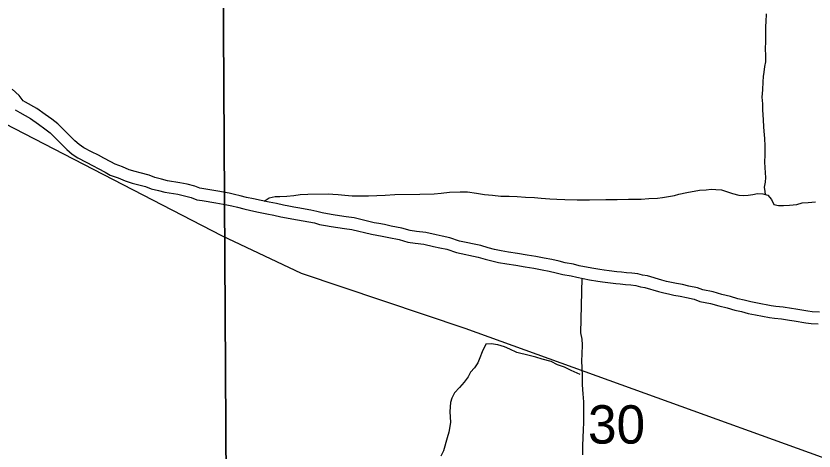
# Model space of a CAD drawing. Extents: x 0 to 34, y 0 to 22.
# Drawn here: x 3.385 to 4.256, y 19.88 to 20.355 of the extents above; entities that cross this region are included whole.
import ezdxf

# ---------------------------------------------------------------- set-up
doc = ezdxf.new("R2010")
doc.units = 0
for name, color, linetype in [('GM_X_Minor_River', 7, 'Continuous'), ('GM_X_Rail_Line', 7, 'Continuous'), ('GM_X_Section', 7, 'Continuous'), ('GM_X_Section_Text', 7, 'Continuous')]:
    doc.layers.add(name, color=color, linetype=linetype)

msp = doc.modelspace()

# ---------------------------------------------------------------- linework, layer by layer
at = {"layer": 'GM_X_Minor_River'}
for points in [[(4.20272, 20.16012), (4.2024, 20.16325), (4.20162, 20.16819), (4.20273, 20.17352), (4.20308, 20.17846), (4.20268, 20.18378), (4.20186, 20.19518), (4.20219, 20.20317), (4.20217, 20.20811), (4.20252, 20.21306), (4.2021, 20.22104), (4.2013, 20.22902), (4.20089, 20.23396), (4.20047, 20.24156), (4.20007, 20.24688), (4.19966, 20.25259), (4.19962, 20.25905), (4.19921, 20.26627), (4.19992, 20.27426), (4.20026, 20.28301), (4.20061, 20.28871), (4.20134, 20.29366), (4.20206, 20.29974), (4.20318, 20.30469), (4.20314, 20.31077), (4.20272, 20.31952), (4.20306, 20.32636), (4.203, 20.33853), (4.20297, 20.34347), (4.20333, 20.34842), (4.20366, 20.35716)], [(3.71354, 20.14163), (3.70699, 20.14283), (3.70091, 20.14395), (3.69477, 20.14507), (3.68838, 20.14617), (3.68275, 20.14727), (3.67698, 20.14833), (3.66946, 20.15017), (3.66161, 20.15171), (3.65265, 20.15353), (3.64424, 20.15541), (3.63686, 20.15685), (3.62994, 20.15864), (3.62357, 20.16021), (3.61787, 20.1614), (3.6055, 20.16367), (3.59035, 20.16632), (3.58603, 20.16687), (3.58032, 20.1692), (3.57195, 20.17136), (3.56412, 20.17298), (3.55047, 20.17513), (3.54409, 20.17687), (3.53686, 20.17856), (3.53052, 20.18114), (3.52097, 20.18359), (3.5155, 20.18503), (3.5089, 20.18698), (3.50155, 20.19025), (3.49339, 20.19305), (3.48901, 20.19553), (3.48123, 20.19977), (3.4753, 20.2029), (3.46773, 20.20665), (3.45938, 20.21113), (3.45445, 20.21449), (3.44962, 20.21864), (3.43113, 20.23698), (3.42461, 20.24216), (3.4174, 20.24732), (3.40811, 20.25373), (3.39568, 20.26088), (3.3931, 20.26226), (3.38877, 20.26809), (3.38125, 20.27508)], [(3.38448, 20.25225), (3.38943, 20.24962), (3.40123, 20.24283), (3.40999, 20.23678), (3.41685, 20.23187), (3.42257, 20.22734), (3.44088, 20.20917), (3.4466, 20.20425), (3.45269, 20.2001), (3.46182, 20.1952), (3.46944, 20.19143), (3.47514, 20.18842), (3.48276, 20.18427), (3.48808, 20.18125), (3.49683, 20.17825), (3.50444, 20.17486), (3.51204, 20.17262), (3.51774, 20.17112), (3.52648, 20.16888), (3.53294, 20.16625), (3.54092, 20.16438), (3.54776, 20.16252), (3.56182, 20.1603), (3.56904, 20.15881), (3.57626, 20.15694), (3.58272, 20.15431), (3.58842, 20.15358), (3.60323, 20.15098), (3.61539, 20.14876), (3.62071, 20.14764), (3.62679, 20.14615), (3.63401, 20.14428), (3.64161, 20.1428), (3.64997, 20.14093), (3.65908, 20.13907), (3.66668, 20.13759), (3.67428, 20.13572), (3.68036, 20.13461), (3.68606, 20.1335), (3.69251, 20.13238), (3.69859, 20.13127), (3.70467, 20.13016), (3.71075, 20.12905)], [(3.65592, 20.15287), (3.66165, 20.15658), (3.66809, 20.15775), (3.67303, 20.15777), (3.68061, 20.15818), (3.6882, 20.15898), (3.6954, 20.16015), (3.70375, 20.16057), (3.72576, 20.16067), (3.73108, 20.16032), (3.73677, 20.15996), (3.74399, 20.15924), (3.75196, 20.15851), (3.7698, 20.15859), (3.78801, 20.15944), (3.79863, 20.16025), (3.82595, 20.16037), (3.84151, 20.16083), (3.8491, 20.16162), (3.8582, 20.1628), (3.86958, 20.16286), (3.87793, 20.16289), (3.88743, 20.16142), (3.89616, 20.15994), (3.9049, 20.15922), (3.91401, 20.15812), (3.92312, 20.15816), (3.93185, 20.15782), (3.94096, 20.1571), (3.95083, 20.15677), (3.95804, 20.15604), (3.96753, 20.15532), (3.97513, 20.15498), (3.98386, 20.15464), (3.99752, 20.15432), (4.0108, 20.15438), (4.02864, 20.15447), (4.04078, 20.15452), (4.0533, 20.15496), (4.06697, 20.15502), (4.07531, 20.15582), (4.0848, 20.15624), (4.09049, 20.15665), (4.10338, 20.15899), (4.1083, 20.16053), (4.11702, 20.16209), (4.13067, 20.16482), (4.13788, 20.16523), (4.14357, 20.16602), (4.1485, 20.16566), (4.15458, 20.16531), (4.16028, 20.16344), (4.16674, 20.16118), (4.17358, 20.15931), (4.17852, 20.15896), (4.18383, 20.15936), (4.18876, 20.16014), (4.19407, 20.16131), (4.19976, 20.16095), (4.20508, 20.15946), (4.20928, 20.15454), (4.21197, 20.14923), (4.2169, 20.14811), (4.22222, 20.14813), (4.22905, 20.14854), (4.23701, 20.14934), (4.2427, 20.15089), (4.24915, 20.1513), (4.25711, 20.15209)], [(4.26151, 20.03187), (4.25362, 20.03222), (4.24872, 20.03285), (4.23593, 20.03505), (4.23098, 20.0358), (4.2219, 20.03733), (4.21405, 20.03808), (4.20898, 20.03873), (4.19414, 20.04164), (4.18655, 20.04305), (4.17944, 20.04489), (4.17255, 20.04631), (4.16441, 20.04886), (4.15514, 20.05114), (4.14569, 20.05385), (4.13439, 20.05599), (4.1285, 20.05817), (4.11926, 20.06023), (4.11205, 20.0618), (4.10548, 20.06287), (4.10007, 20.06428), (4.09475, 20.0654), (4.08959, 20.06675), (4.0741, 20.07145), (4.06871, 20.07225), (4.06364, 20.0734), (4.05692, 20.07427), (4.05123, 20.07462), (4.04559, 20.07535), (4.04064, 20.07571), (4.03226, 20.07676), (4.02671, 20.07748), (4.02198, 20.07818), (4.01325, 20.0796), (3.9997, 20.08247), (3.99332, 20.08404), (3.98428, 20.0855), (3.97756, 20.08724), (3.96958, 20.0892), (3.96148, 20.09078), (3.95212, 20.0923), (3.94274, 20.09376), (3.93244, 20.09562), (3.9225, 20.09711), (3.91435, 20.09849), (3.90728, 20.10023), (3.90035, 20.10202), (3.89244, 20.10436), (3.86921, 20.10912), (3.85851, 20.1129), (3.85012, 20.11454), (3.84358, 20.11596), (3.83232, 20.11873), (3.82216, 20.1199), (3.81517, 20.12087), (3.80606, 20.12338), (3.79462, 20.1257), (3.78729, 20.1272), (3.78115, 20.12833), (3.77583, 20.12937), (3.7542, 20.13468), (3.74561, 20.13587), (3.73811, 20.13696), (3.73112, 20.13803), (3.72516, 20.13913), (3.71918, 20.14016), (3.71354, 20.14163)], [(3.71075, 20.12905), (3.71645, 20.12755), (3.72291, 20.12644), (3.72898, 20.12533), (3.7362, 20.12422), (3.7438, 20.12312), (3.75177, 20.12201), (3.77305, 20.11679), (3.77875, 20.11567), (3.78483, 20.11456), (3.79205, 20.11307), (3.80306, 20.11084), (3.81256, 20.10822), (3.82054, 20.10712), (3.83003, 20.10602), (3.84067, 20.10341), (3.84751, 20.10192), (3.85511, 20.10044), (3.86576, 20.09668), (3.88931, 20.09185), (3.89691, 20.0896), (3.90413, 20.08773), (3.91173, 20.08587), (3.92047, 20.08439), (3.93034, 20.08291), (3.9406, 20.08106), (3.9501, 20.07958), (3.95921, 20.0781), (3.96681, 20.07662), (3.97441, 20.07475), (3.98163, 20.07288), (3.99075, 20.0714), (3.99683, 20.06991), (4.01088, 20.06693), (4.02, 20.06545), (4.02494, 20.06472), (4.03063, 20.06398), (4.03937, 20.06288), (4.0443, 20.06252), (4.05, 20.06179), (4.05569, 20.06144), (4.06139, 20.0607), (4.06633, 20.05958), (4.07127, 20.05885), (4.08609, 20.05435), (4.09179, 20.05286), (4.09711, 20.05174), (4.10281, 20.05025), (4.10965, 20.04914), (4.11649, 20.04765), (4.12485, 20.04579), (4.13093, 20.04353), (4.14271, 20.0413), (4.15183, 20.03869), (4.16095, 20.03645), (4.16931, 20.03382), (4.17653, 20.03234), (4.18375, 20.03047), (4.19173, 20.02898), (4.20692, 20.02601), (4.21262, 20.02528), (4.22021, 20.02455), (4.22895, 20.02307), (4.23389, 20.02233), (4.2468, 20.02011), (4.2525, 20.01938), (4.26009, 20.01903)], [(4.00228, 20.06876), (4.00083, 20.00916), (4.00237, 20.00231), (4.00277, 19.99623), (4.00241, 19.98596), (4.00205, 19.97874), (4.00245, 19.97113), (4.00285, 19.96238), (4.00288, 19.9525), (4.00366, 19.94261), (4.00407, 19.93386), (4.00412, 19.91143), (4.00376, 19.90344), (4.0034, 19.89508), (4.00304, 19.88595), (4.00306, 19.87606)], [(4.00056, 19.96391), (3.99063, 19.96809), (3.98337, 19.9719), (3.97573, 19.97419), (3.96885, 19.97799), (3.9593, 19.98066), (3.95243, 19.98256), (3.94517, 19.98447), (3.93143, 19.9879), (3.92379, 19.99133), (3.91805, 19.99399), (3.9108, 19.99628), (3.90355, 19.99742), (3.89782, 19.99705), (3.89364, 19.98868), (3.89137, 19.98184), (3.88909, 19.97652), (3.88529, 19.97119), (3.8811, 19.96625), (3.87844, 19.96131), (3.87426, 19.95561), (3.86893, 19.94953), (3.8636, 19.94383), (3.86056, 19.93812), (3.85905, 19.93318), (3.85831, 19.92329), (3.8591, 19.9115), (3.85722, 19.90086), (3.85571, 19.89477), (3.85154, 19.88071), (3.8485, 19.87462)]]:
    msp.add_lwpolyline(points, dxfattribs=at)
at = {"layer": 'GM_X_Rail_Line'}
msp.add_lwpolyline([(2.71547, 20.89996), (2.72998, 20.88092), (3.04126, 20.47986), (3.13084, 20.36736), (3.16829, 20.34314), (3.60958, 20.11538), (3.69621, 20.0743), (3.87472, 20.01418), (4.47269, 19.79857), (4.53515, 19.76529), (4.57408, 19.73231), (4.625, 19.67685), (4.95604, 19.29764)], dxfattribs=at)
at = {"layer": 'GM_X_Section'}
for points in [[(3.61209, 20.42238), (4.4682, 20.4307), (4.46617, 19.4189), (3.61727, 19.41058), (3.61142, 20.40305)], [(3.61142, 20.40305), (3.61727, 19.41058), (3.61773, 19.39391), (2.62685, 19.38749), (2.61399, 20.39532)]]:
    msp.add_lwpolyline(points, close=True, dxfattribs=at)

# ---------------------------------------------------------------- texts
at = {"layer": 'GM_X_Section_Text'}
msp.add_text('30', height=0.041856, rotation=0.00001, dxfattribs=at).set_placement((4.00915, 19.88843))

doc.saveas('drawing.dxf')
